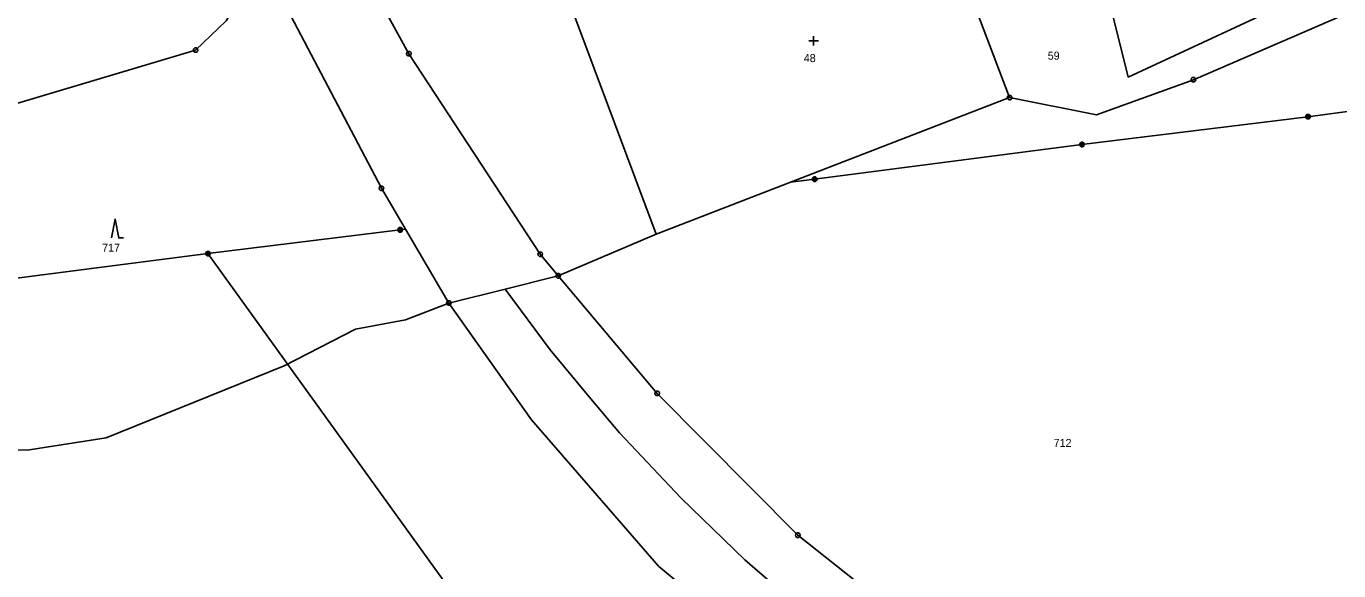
# Model space of a CAD drawing. Extents: x -812394 to -807601, y -1013098 to -1009266.
# Drawn here: x -809886.4 to -809607.5, y -1011158.1 to -1011042.4 of the extents above; entities that cross this region are included whole.
import ezdxf

# ---------------------------------------------------------------- set-up
doc = ezdxf.new("R2010")
doc.units = 0
for name, color, linetype in [('KN_HRANICE', 7, 'Continuous'), ('KN_KULTURY', 7, 'Continuous'), ('KN_MEZNIKY', 7, 'Continuous'), ('KN_PARCELY', 7, 'Continuous'), ('KN_VEDENI', 7, 'Continuous')]:
    doc.layers.add(name, color=color, linetype=linetype)

# ---------------------------------------------------------------- blocks, each defined once
blk = doc.blocks.new('308')
blk.add_lwpolyline([(-0.75, 0), (0, 4), (0.75, 0), (1.75, 0)])
blk = doc.blocks.new('315')
for p, q in [((-1, 1), (1, 1)), ((0, 0), (0, 2))]:
    blk.add_line(p, q)
blk = doc.blocks.new('105')
blk.add_line((-0.12, 0), (0.12, 0))
blk.add_lwpolyline([(0.15, 0.48), (0.4, 0.3), (0.5, 0.01), (0.4, -0.28), (0.15, -0.46), (-0.16, -0.46), (-0.41, -0.28), (-0.51, 0.01), (-0.41, 0.3), (-0.16, 0.48), (0.15, 0.48)])
blk = doc.blocks.new('601')
blk.add_lwpolyline([(-0.15, 0.48), (0.16, 0.48), (0.41, 0.3), (0.51, 0.01), (0.41, -0.28), (0.16, -0.46), (-0.15, -0.46), (-0.4, -0.28), (-0.5, 0.01), (-0.4, 0.3), (-0.15, 0.48), (-0.12, 0.44), (0.12, 0.44), (0.28, 0.36), (-0.28, 0.36), (-0.36, 0.28), (0.36, 0.28), (0.36, 0.2), (-0.36, 0.2), (-0.4, 0.12), (0.4, 0.12), (0.44, 0.04), (-0.44, 0.04), (-0.44, -0.04), (0.44, -0.04), (0.41, -0.12), (-0.4, -0.12), (-0.39, -0.2), (0.42, -0.2), (0.37, -0.28), (-0.35, -0.28), (-0.27, -0.36), (0.29, -0.36), (0.18, -0.44), (-0.16, -0.44)])

msp = doc.modelspace()

# ---------------------------------------------------------------- linework, layer by layer
at = {"layer": 'KN_HRANICE'}
for p, q in [((-809817.83, -1011024.91), (-809805.06, -1011048.21)), ((-809836.26, -1011028.53), (-809810.89, -1011076.81)), ((-809652.22, -1011053.19), (-809658.63, -1011027.44)), ((-809638.37, -1011053.74), (-809581.58, -1011029.19)), ((-809603.78, -1011030.67), (-809652.22, -1011053.19)), ((-809752.49, -1011086.54), (-809770.25, -1011039.27)), ((-809677.42, -1011057.54), (-809684.4, -1011039.22)), ((-809805.06, -1011048.21), (-809777.13, -1011090.84)), ((-809658.97, -1011061.19), (-809638.37, -1011053.74)), ((-809752.49, -1011086.54), (-809677.42, -1011057.54)), ((-809677.42, -1011057.54), (-809658.97, -1011061.19)), ((-809810.89, -1011076.81), (-809796.54, -1011101.19)), ((-809773.31, -1011095.41), (-809752.49, -1011086.54)), ((-809777.13, -1011090.84), (-809773.31, -1011095.41)), ((-809784.6, -1011098.22), (-809773.31, -1011095.41)), ((-809796.54, -1011101.19), (-809784.6, -1011098.22)), ((-809779.01, -1011125.97), (-809796.54, -1011101.19)), ((-809751.99, -1011157.11), (-809779.01, -1011125.97)), ((-809719.22, -1011184.3), (-809751.99, -1011157.11))]:
    msp.add_line(p, q, dxfattribs=at)
for points in [[(-809836.26, -1011028.53), (-809843.91, -1011041.24), (-809850.36, -1011047.46), (-809913.17, -1011066.15), (-809940.27, -1011066.63), (-809925.64, -1011129.13), (-809925.02, -1011131.63)], [(-809773.31, -1011095.41), (-809752.3, -1011120.38), (-809722.41, -1011150.52), (-809685.06, -1011180.11), (-809638.61, -1011207.44), (-809624.45, -1011211.08)], [(-809925.02, -1011131.63), (-809914.36, -1011132.31), (-809886.15, -1011132.43), (-809869.35, -1011129.81), (-809831.58, -1011114.54), (-809816.37, -1011106.77), (-809805.79, -1011104.77), (-809796.54, -1011101.19)]]:
    msp.add_lwpolyline(points, dxfattribs=at)
at = {"layer": 'KN_VEDENI'}
for p, q in [((-809847.74, -1011090.69), (-809806.91, -1011085.64)), ((-809806.91, -1011085.64), (-809805.77, -1011085.5)), ((-809775.03, -1011111.13), (-809784.6, -1011098.22)), ((-809766.04, -1011121.98), (-809775.03, -1011111.13)), ((-809760.29, -1011128.79), (-809766.04, -1011121.98)), ((-809747.26, -1011142.59), (-809760.29, -1011128.79)), ((-809733.68, -1011155.72), (-809747.26, -1011142.59)), ((-809718.98, -1011168.43), (-809733.68, -1011155.72))]:
    msp.add_line(p, q, dxfattribs=at)
for points in [[(-809723.95, -1011075.51), (-809718.84, -1011074.89), (-809662.06, -1011067.52), (-809614.03, -1011061.6), (-809568.87, -1011055.54)], [(-809847.74, -1011090.69), (-809935.67, -1011101.99), (-810048.36, -1011116.35), (-810161.44, -1011130.66), (-810270.03, -1011144.67), (-810376.1, -1011158.31), (-810487.14, -1011172.35), (-810591.19, -1011185.57), (-810690.15, -1011198.24), (-810781.09, -1011209.76), (-810822.35, -1011215), (-810862.42, -1011220.06)], [(-809530.59, -1011529.94), (-809540.27, -1011516.97), (-809550.43, -1011502.66), (-809602.98, -1011429.8), (-809656.35, -1011356.06), (-809708.6, -1011283), (-809752.29, -1011222.71), (-809798.63, -1011158.84), (-809847.74, -1011090.69)]]:
    msp.add_lwpolyline(points, dxfattribs=at)

# ---------------------------------------------------------------- block references
at = {"layer": 'KN_KULTURY'}
for name, p in [('315', (-809719.06, -1011046.5)), ('308', (-809867.46, -1011087.35))]:
    msp.add_blockref(name, p, dxfattribs=at)
at = {"layer": 'KN_MEZNIKY'}
for p in [(-809850.36, -1011047.46), (-809805.06, -1011048.21), (-809638.37, -1011053.74), (-809677.42, -1011057.54), (-809810.89, -1011076.81), (-809777.13, -1011090.84), (-809773.31, -1011095.41), (-809796.54, -1011101.19), (-809752.3, -1011120.38), (-809722.41, -1011150.52)]:
    msp.add_blockref('105', p, dxfattribs=at)
at = {"layer": 'KN_VEDENI'}
for p in [(-809614.03, -1011061.6), (-809662.06, -1011067.52), (-809718.84, -1011074.89), (-809806.91, -1011085.64), (-809847.74, -1011090.69)]:
    msp.add_blockref('601', p, dxfattribs=at)

# ---------------------------------------------------------------- texts
at = {"layer": 'KN_PARCELY'}
for s, p in [('48', (-809721.15, -1011050)), ('59', (-809669.32, -1011049.48)), ('717', (-809870.22, -1011090.28)), ('712', (-809668.06, -1011131.76))]:
    msp.add_text(s, height=1.7, dxfattribs=at).set_placement(p)

doc.saveas('drawing.dxf')
